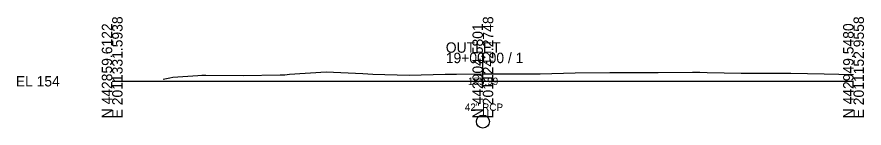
# Model space of a CAD drawing. Extents: x -26 to 1203, y -15 to 9526.
# Drawn here: x -25.7 to 202.8, y 8987.4 to 9017.3 of the extents above; entities that cross this region are included whole.
import ezdxf

# ---------------------------------------------------------------- set-up
doc = ezdxf.new("R2010")
doc.units = 0
for name, color, linetype in [('Exist Cross Section Cell', 7, 'Continuous'), ('Exist XS Center Line Elevation Label', 7, 'Continuous'), ('Exist XS Ground Line', 7, 'Continuous'), ('Prop XSC Text', 7, 'Continuous')]:
    doc.layers.add(name, color=color, linetype=linetype)

msp = doc.modelspace()

# ---------------------------------------------------------------- linework, layer by layer
at = {"layer": 'Exist Cross Section Cell'}
for p, q in [((100, 9000), (100, 9007.69)), ((0, 9000), (100, 9000)), ((100, 9000), (200, 9000))]:
    msp.add_line(p, q, dxfattribs=at)
at = {"layer": 'Exist XS Ground Line'}
msp.add_lwpolyline([(13.72, 9000.58), (15.52, 9000.94), (16.37, 9001.1), (23.1, 9001.57), (24.18, 9001.62), (25.27, 9001.63), (35.37, 9001.55), (45.34, 9001.74), (46.57, 9001.76), (47.81, 9001.87), (57.76, 9002.56), (67.58, 9002.07), (68.96, 9001.98), (70.36, 9001.95), (80.16, 9001.67), (89.81, 9001.91), (91.35, 9001.93), (92.91, 9001.94), (100, 9001.99), (102.55, 9002), (112.05, 9001.96), (113.74, 9001.98), (115.46, 9002.01), (124.94, 9002.24), (134.29, 9002.35), (136.13, 9002.37), (138, 9002.38), (147.33, 9002.4), (156.53, 9002.41), (158.53, 9002.41), (160.55, 9002.38), (169.72, 9002.19), (172.75, 9002.17), (178.77, 9002.2), (180.92, 9002.19), (183.1, 9002.14), (192.11, 9002.02), (200, 9001.83)], dxfattribs=at)
at = {"layer": 'Prop XSC Text'}
msp.add_circle((100, 8989.15), 1.75, dxfattribs=at)

# ---------------------------------------------------------------- texts
at = {"layer": 'Exist Cross Section Cell'}
for s, p in [('E 2011331.5938', (2.8, 8990)), ('E 2011242.2748', (102.8, 8990)), ('E 2011152.9558', (202.8, 8990)), ('N 442859.6122', (0, 8990)), ('N 442904.5801', (100, 8990)), ('N 442949.5480', (200, 8990))]:
    msp.add_text(s, height=2.8, rotation=90, dxfattribs=at).set_placement(p)
for s, p in [('OUTLET', (90, 9007.69)), ('19+00.00 / 1', (90, 9004.89)), ('EL 154', (-26, 8998.6))]:
    msp.add_text(s, height=2.8, dxfattribs=at).set_placement(p)
at = {"layer": 'Exist XS Center Line Elevation Label'}
msp.add_text('155.99', height=2, dxfattribs=at).set_placement((95.97, 8998.99))
at = {"layer": 'Prop XSC Text'}
msp.add_text('42" RCP', height=2, dxfattribs=at).set_placement((95.14, 8992.01))

doc.saveas('drawing.dxf')
